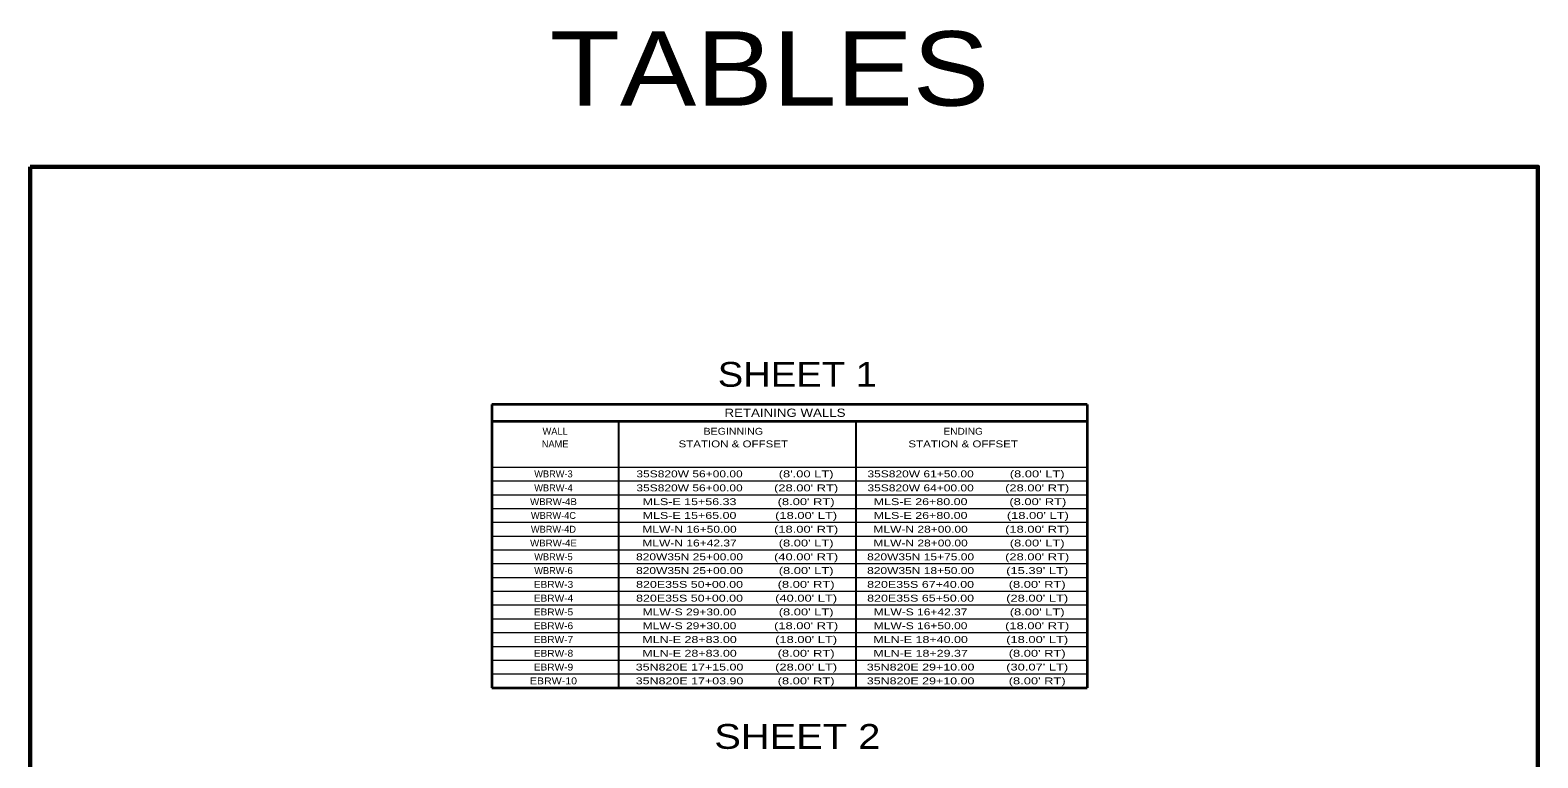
# Model space of a CAD drawing. Extents: x 2319482 to 2362028, y 6981189 to 6994467.
# Drawn here: x 2319482 to 2322105, y 6984659 to 6985926 of the extents above; entities that cross this region are included whole.
import ezdxf
from ezdxf.enums import TextEntityAlignment as Align

# ---------------------------------------------------------------- set-up
doc = ezdxf.new("R2010")
doc.units = 0
doc.header["$LTSCALE"] = 4.8
doc.layers.add('26', color=7, linetype='Continuous', lineweight=13)
doc.layers.add('63', color=7, linetype='Continuous', lineweight=60)

msp = doc.modelspace()

# ---------------------------------------------------------------- linework, layer by layer
at = {"layer": '26', "lineweight": 35}
for p, q in [((2321320.984, 6985273.881), (2320285.241, 6985273.881)), ((2320285.241, 6985273.881), (2320285.241, 6984780.748)), ((2321320.984, 6985273.881), (2321320.984, 6984780.748)), ((2320285.241, 6985245.081), (2321320.984, 6985245.081)), ((2320285.241, 6984780.748), (2321320.984, 6984780.748))]:
    msp.add_line(p, q, dxfattribs=at)
at = {"layer": '26', "lineweight": 25}
for p, q in [((2320505.241, 6985245.081), (2320505.241, 6984780.748)), ((2320918.76, 6985245.081), (2320918.76, 6984780.748))]:
    msp.add_line(p, q, dxfattribs=at)
at = {"layer": '26'}
for p, q in [((2320285.241, 6985164.748), (2321320.984, 6985164.748)), ((2320285.241, 6985140.748), (2321320.984, 6985140.748)), ((2320285.241, 6985116.748), (2321320.984, 6985116.748)), ((2320285.241, 6985092.748), (2321320.984, 6985092.748)), ((2320285.241, 6985068.748), (2321320.984, 6985068.748)), ((2320285.241, 6985044.748), (2321320.984, 6985044.748)), ((2320285.241, 6985020.748), (2321320.984, 6985020.748)), ((2320285.241, 6984996.748), (2321320.984, 6984996.748)), ((2320285.241, 6984972.748), (2321320.984, 6984972.748)), ((2320285.241, 6984948.748), (2321320.984, 6984948.748)), ((2320285.241, 6984924.748), (2321320.984, 6984924.748)), ((2320285.241, 6984900.748), (2321320.984, 6984900.748)), ((2320285.241, 6984876.748), (2321320.984, 6984876.748)), ((2320285.241, 6984852.748), (2321320.984, 6984852.748)), ((2320285.241, 6984828.748), (2321320.984, 6984828.748)), ((2320285.241, 6984804.748), (2321320.984, 6984804.748))]:
    msp.add_line(p, q, dxfattribs=at)
at = {"layer": '63'}
msp.add_lwpolyline([(2319481.784, 6985687.71), (2322105.179, 6985687.71), (2322105.179, 6981188.674), (2319481.784, 6981188.674)], close=True, dxfattribs=at)

# ---------------------------------------------------------------- texts
at = {"layer": '26'}
for s, height, width, p in [('TABLES', 129.6, 1.15, (2320768.313, 6985794.069)), ('SHEET 1', 43.2, 1.15, (2320816.684, 6985304.69)), ('RETAINING WALLS', 14.4, 1.2, (2320795.235, 6985252.277)), ('STATION & OFFSET', 12, 1.25, (2320705.236, 6985199.201)), ('BEGINNING', 12, 1.15, (2320705.237, 6985221.201)), ('STATION & OFFSET', 12, 1.25, (2321105.235, 6985199.201)), ('ENDING', 12, 1.1, (2321105.237, 6985221.2)), ('35S820W 56+00.00', 12, 1.3, (2320629.13, 6985147.031)), ("(8'.00 LT)", 12, 1.4, (2320831.972, 6985147.031)), ('35S820W 61+50.00', 12, 1.3, (2321031.175, 6985147.031)), ("(8.00' LT)", 12, 1.4, (2321234.017, 6985147.031)), ('35S820W 56+00.00', 12, 1.3, (2320629.129, 6985122.653)), ("(28.00' RT)", 12, 1.4, (2320831.971, 6985122.652)), ('35S820W 64+00.00', 12, 1.3, (2321031.174, 6985122.653)), ("(28.00' RT)", 12, 1.4, (2321234.016, 6985122.652)), ('WBRW-4B', 12, 1.05, (2320392.349, 6985098.655)), ('MLS-E 15+56.33', 12, 1.35, (2320629.128, 6985098.653)), ("(8.00' RT)", 12, 1.4, (2320831.972, 6985098.652)), ('MLS-E 26+80.00', 12, 1.35, (2321031.173, 6985098.653)), ("(8.00' RT)", 12, 1.4, (2321235.177, 6985098.652)), ('MLS-E 15+65.00', 12, 1.35, (2320629.128, 6985074.653)), ("(18.00' LT)", 12, 1.4, (2320831.971, 6985074.652)), ('MLS-E 26+80.00', 12, 1.35, (2321031.173, 6985074.653)), ("(18.00' LT)", 12, 1.4, (2321235.176, 6985074.652)), ('MLW-N 16+50.00', 12, 1.3, (2320629.128, 6985050.653)), ("(18.00' RT)", 12, 1.4, (2320831.971, 6985050.652)), ('MLW-N 28+00.00', 12, 1.3, (2321031.173, 6985050.653)), ("(18.00' RT)", 12, 1.4, (2321234.016, 6985050.652)), ('WBRW-4E', 12, 1.05, (2320392.349, 6985026.655)), ('MLW-N 16+42.37', 12, 1.3, (2320629.128, 6985026.653)), ("(8.00' LT)", 12, 1.4, (2320831.972, 6985026.652)), ('MLW-N 28+00.00', 12, 1.3, (2321031.173, 6985026.653)), ("(8.00' LT)", 12, 1.4, (2321234.017, 6985026.652)), ('820W35N 25+00.00', 12, 1.3, (2320629.128, 6985002.653)), ("(40.00' RT)", 12, 1.4, (2320831.97, 6985002.652)), ('820W35N 15+75.00', 12, 1.3, (2321031.173, 6985002.653)), ("(28.00' RT)", 12, 1.4, (2321234.015, 6985002.652)), ('820W35N 25+00.00', 12, 1.3, (2320629.128, 6984978.652)), ("(8.00' LT)", 12, 1.4, (2320831.971, 6984978.652)), ('820W35N 18+50.00', 12, 1.3, (2321031.173, 6984978.652)), ("(15.39' LT)", 12, 1.4, (2321234.015, 6984978.652)), ('EBRW-3', 12, 1.1, (2320392.349, 6984954.654)), ('820E35S 50+00.00', 12, 1.35, (2320629.128, 6984954.652)), ("(8.00' RT)", 12, 1.4, (2320831.971, 6984954.652)), ('820E35S 67+40.00', 12, 1.35, (2321031.173, 6984954.652)), ("(8.00' RT)", 12, 1.4, (2321234.016, 6984954.652)), ('EBRW-4', 12, 1.1, (2320392.349, 6984930.654)), ('820E35S 50+00.00', 12, 1.35, (2320629.129, 6984930.652)), ("(40.00' LT)", 12, 1.4, (2320831.971, 6984930.651)), ('820E35S 65+50.00', 12, 1.35, (2321031.174, 6984930.652)), ("(28.00' LT)", 12, 1.4, (2321234.015, 6984930.651)), ('EBRW-5', 12, 1.1, (2320392.349, 6984906.653)), ('EBRW-6', 12, 1.1, (2320392.349, 6984882.653)), ('MLW-S 29+30.00', 12, 1.3, (2320629.128, 6984906.653)), ('MLW-S 29+30.00', 12, 1.3, (2320629.128, 6984882.653)), ("(18.00' RT)", 12, 1.4, (2320831.971, 6984882.651)), ("(8.00' LT)", 12, 1.4, (2320831.971, 6984906.652)), ('MLW-S 16+42.37', 12, 1.3, (2321031.173, 6984906.652)), ('MLW-S 16+50.00', 12, 1.3, (2321031.173, 6984882.653)), ("(18.00' RT)", 12, 1.4, (2321234.016, 6984882.651)), ("(8.00' LT)", 12, 1.4, (2321234.016, 6984906.652)), ('EBRW-7', 12, 1.1, (2320392.348, 6984858.655)), ('MLN-E 28+83.00', 12, 1.35, (2320629.127, 6984858.653)), ("(18.00' LT)", 12, 1.4, (2320831.97, 6984858.652)), ('MLN-E 18+40.00', 12, 1.35, (2321031.172, 6984858.653)), ("(18.00' LT)", 12, 1.4, (2321234.015, 6984858.652)), ('EBRW-8', 12, 1.1, (2320392.348, 6984834.654)), ('MLN-E 28+83.00', 12, 1.35, (2320629.127, 6984834.653)), ("(8.00' RT)", 12, 1.4, (2320831.97, 6984834.652)), ('MLN-E 18+29.37', 12, 1.35, (2321031.172, 6984834.653)), ("(8.00' RT)", 12, 1.4, (2321234.015, 6984834.652)), ('EBRW-9', 12, 1.1, (2320392.348, 6984810.654)), ('35N820E 17+15.00', 12, 1.35, (2320629.128, 6984810.652)), ("(28.00' LT)", 12, 1.4, (2320831.97, 6984810.652)), ('35N820E 29+10.00', 12, 1.35, (2321031.173, 6984810.652)), ("(30.07' LT)", 12, 1.4, (2321234.015, 6984810.652)), ('EBRW-10', 12, 1.15, (2320392.35, 6984786.654)), ('35N820E 17+03.90', 12, 1.35, (2320629.128, 6984786.652)), ("(8.00' RT)", 12, 1.4, (2320831.971, 6984786.652)), ('35N820E 29+10.00', 12, 1.35, (2321031.173, 6984786.652)), ("(8.00' RT)", 12, 1.4, (2321234.015, 6984786.652)), ('SHEET 2', 43.2, 1.2, (2320816.684, 6984674.313))]:
    msp.add_text(s, height=height, dxfattribs=dict(at, width=width)).set_placement(p, align=Align.CENTER)
for s, p in [('NAME', (2320395.235, 6985199.201)), ('WALL', (2320395.236, 6985221.201)), ('WBRW-3', (2320392.35, 6985147.033)), ('WBRW-4', (2320392.349, 6985122.655)), ('WBRW-4C', (2320392.349, 6985074.655)), ('WBRW-4D', (2320392.349, 6985050.655)), ('WBRW-5', (2320392.349, 6985002.654)), ('WBRW-6', (2320392.349, 6984978.654))]:
    msp.add_text(s, height=12, dxfattribs=at).set_placement(p, align=Align.CENTER)

doc.saveas('drawing.dxf')
